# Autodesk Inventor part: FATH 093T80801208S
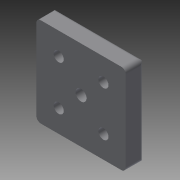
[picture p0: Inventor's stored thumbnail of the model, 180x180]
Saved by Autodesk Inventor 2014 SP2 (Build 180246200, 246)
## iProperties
Created: 2018-10
Part Number: FATH 093T80801208S
Material: Generic
Catalog Web Link: www.cadenas.de
Description: Transport and Base Plate 80 x 80-Die-cast Zinc
Vendor: FATH
Document SubType Name: Modeling
Designer: psadmin
Manufacturer: FATH
Mass: 92.2202 g
Surface Area: 197.085 cm^2
Volume: 92.2202 cm^3
Density: 1 g/cm^3
Appearance: PSOLRGB-175-175-175
Category: PARTsolutions
Company: FATH
Title: FATH 093T80801208S
Author: Cadenas PARTsolutions
Comments: Die-cast Zinc
PSOL_IDENT_0: {$CADENAS_DATA\23d-libs\fath\zubehoer_alu_sys\fussplatten\093t8080.prj},194 {VTYP=3D},{NB=FATH 093T8
PSOL_IDENT_1: 0801208S},{LINA=FATH 093T80801208S},{NN=Transport and Base Plate 80 x 80},{DATE=19.02.2018 15:31:06}
PSOL_IDENT_2: ,{GEOMDATE=26.05.2005},{VERSION=},{LINEID=750},{WBVAR=},{WBNUMERIC=}  {NB=FATH 093T80801208S},{LINA=
PSOL_IDENT_3: FATH 093T80801208S},{KT=DUMMY},{BO=für M8},{D=9.0},{DIM=80x80},{A=40},{M=M12},{O=pulverbeschichtet},
PSOL_IDENT_4: {ARTNR=093T80801208S},{PRTNO=},{L=80},{B=80},{H=16},{D1=9.0},{D2=15},{T=9.0},{GEW=12},{KD=9.9},{R1=4
PSOL_IDENT_5: .0},{R2=3},{FO=2}
NN: Transport- und Fußplatte 80x80
NT: Zinkdruckguss
NB: FATH 093T80801208S
NBSYN: FATH $ARTNR.
LINA: FATH 093T80801208S
BO: für M8
D: 9
DIM: 80x80
A: 40
M: M12
O: pulverbeschichtet
ARTNR: 093T80801208S
SUPPLIER: FATH
ARTICLENO: FATH 093T80801208S
BOMINFO: FATH 093T80801208S
CREATOR: CADENAS GmbH
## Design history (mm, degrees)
sketch "Skizze_1"
  geometry: L1 (36, 40)-(-36, 40); L2 (-40, 36)-(-40, -36); L3 (-36, -40)-(36, -40); L4 (40, -36)-(40, 36); A1 r 4 centre (36, 36) between (40, 36) and (36, 40); A2 r 4 centre (-36, 36) between (-36, 40) and (-40, 36); A3 r 4 centre (-36, -36) between (-40, -36) and (-36, -40); A4 r 4 centre (36, -36) between (36, -40) and (40, -36)
  constraints: 8 end point, 8 point on circle, 4 centre point
extrude "Extrusion1" join sketch "Skizze_1" distance "d0" = 16; taper "d1" = 0 deg
sketch "Skizze_2"
  geometry: L1 (19, 43)-(0, 43); L2 (0, 43)-(0, 40); L3 (0, 40)-(13, 40); L4 (16, 37)-(16, -37); L5 (13, -40)-(0, -40); L6 (0, -40)-(0, -43); L7 (0, -43)-(19, -43); L8 (19, -43)-(19, 43); A1 r 3 centre (13, 37) between (16, 37) and (13, 40); A2 r 3 centre (13, -37) between (13, -40) and (16, -37)
  constraints: 16 end point, 4 point on circle, 2 centre point
extrude "Extrusion2" cut sketch "Skizze_2" stored distance "d2" = 80; taper "d3" = 0 deg
sketch "Skizze_3"
  geometry: L1 (-43, 19)-(-43, 0); L2 (-43, 0)-(-40, 0); L3 (-40, 0)-(-40, 13); L4 (-37, 16)-(37, 16); L5 (40, 13)-(40, 0); L6 (40, 0)-(43, 0); L7 (43, 0)-(43, 19); L8 (43, 19)-(-43, 19); A1 r 3 centre (-37, 13) between (-37, 16) and (-40, 13); A2 r 3 centre (37, 13) between (40, 13) and (37, 16)
  constraints: 16 end point, 4 point on circle, 2 centre point
extrude "Extrusion3" cut sketch "Skizze_3" stored distance "d4" = 80; taper "d5" = 0 deg
sketch "Skizze_7"
  geometry: L1 (-20, 18)-(-20, 0); L2 (-20, 0)-(-24.5, 0); L3 (-24.5, 0)-(-24.5, 7); L4 (-24.5, 7)-(-27.5, 7); L5 (-27.5, 7)-(-27.5, 18); L6 (-27.5, 18)-(-20, 18); L7 (-20, 18)-(-20, 0)
  constraints: 14 end point
revolve "Revolution1" sketch "Skizze_7" stored, may be unused: angle "d6" = 360 deg
sketch "Skizze_8"
  geometry: L1 (20, 18)-(20, 0); L2 (20, 0)-(15.5, 0); L3 (15.5, 0)-(15.5, 7); L4 (15.5, 7)-(12.5, 7); L5 (12.5, 7)-(12.5, 18); L6 (12.5, 18)-(20, 18); L7 (20, 18)-(20, 0)
  constraints: 14 end point
revolve "Revolution2" sketch "Skizze_8" stored, may be unused: angle "d7" = 360 deg
sketch "Skizze_9"
  geometry: L1 (-20, 18)-(-20, 0); L2 (-20, 0)-(-24.5, 0); L3 (-24.5, 0)-(-24.5, 7); L4 (-24.5, 7)-(-27.5, 7); L5 (-27.5, 7)-(-27.5, 18); L6 (-27.5, 18)-(-20, 18); L7 (-20, 18)-(-20, 0)
  constraints: 14 end point
revolve "Revolution3" sketch "Skizze_9" stored, may be unused: angle "d8" = 360 deg
sketch "Skizze_10"
  geometry: L1 (20, 18)-(20, 0); L2 (20, 0)-(15.5, 0); L3 (15.5, 0)-(15.5, 7); L4 (15.5, 7)-(12.5, 7); L5 (12.5, 7)-(12.5, 18); L6 (12.5, 18)-(20, 18); L7 (20, 18)-(20, 0)
  constraints: 14 end point
revolve "Revolution4" sketch "Skizze_10" stored, may be unused: angle "d9" = 360 deg
sketch "Skizze_6"
  geometry: L1 (16, 0)-(0, 0); L2 (0, 0)-(0, 4.95); L3 (0, 4.95)-(16, 4.95); L4 (16, 4.95)-(16, 0); L5 (16, 0)-(0, 0)
  constraints: 10 end point
revolve "Revolution5" sketch "Skizze_6" stored, may be unused: angle "d10" = 360 deg
body "Solid1"
